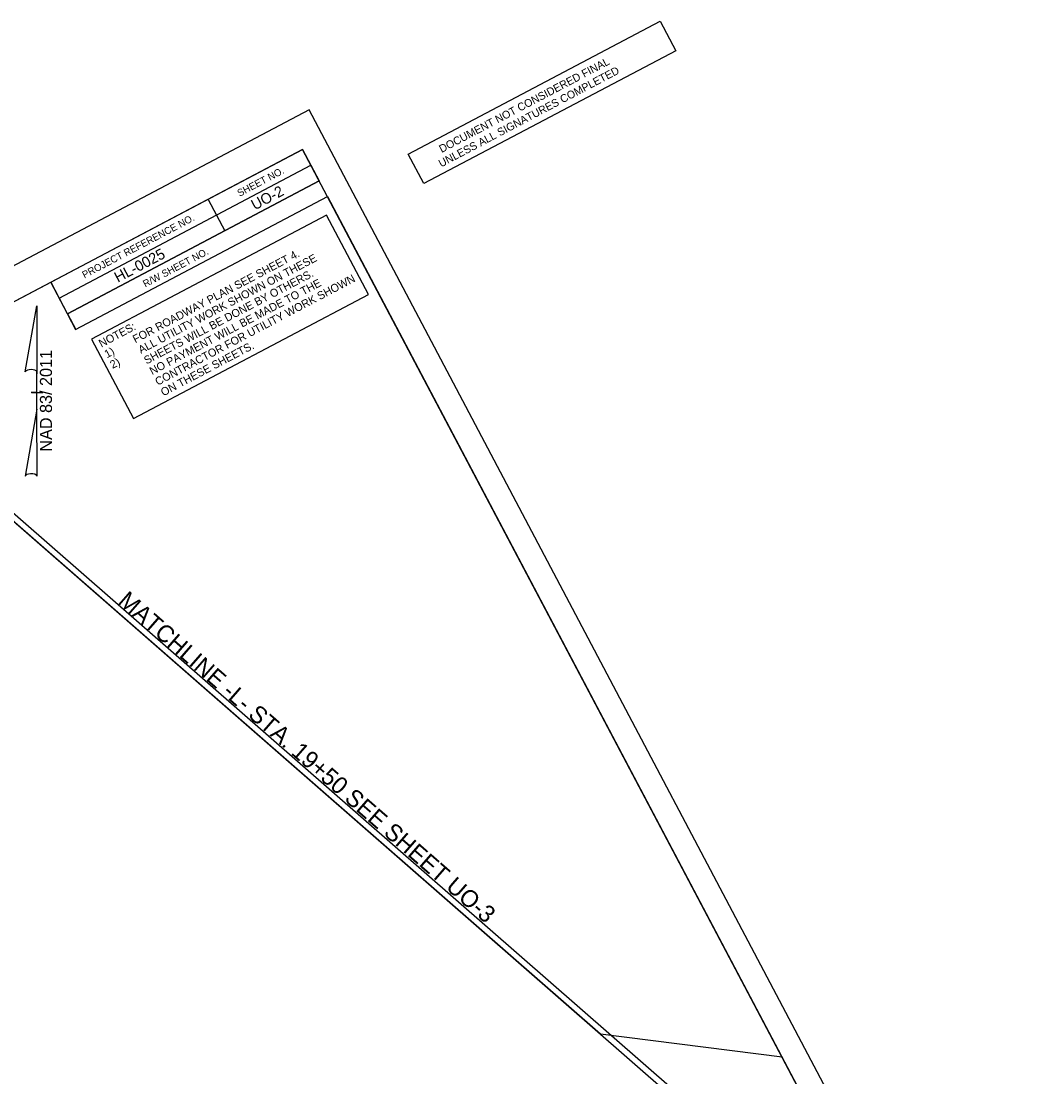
# Model space of a CAD drawing. Extents: x 1487051 to 1489241, y 497582 to 499399.
# Drawn here: x 1488337 to 1489051, y 498657 to 499399 of the extents above; entities that cross this region are included whole.
import ezdxf

# ---------------------------------------------------------------- set-up
doc = ezdxf.new("R2010")
doc.units = 0
for name, color, linetype in [('COGO Default Point Elevation', 7, 'Continuous'), ('Exist DTM Breakline Cogo Elevation', 7, 'Continuous'), ('Exist DTM Breakline Cogo Number', 7, 'Continuous'), ('Exist DTM Regular Point Cogo Elevation', 7, 'Continuous'), ('Exist DTM Regular Point Cogo Number', 7, 'Continuous'), ('Exist Other Culture Sign Post Cogo Comment', 7, 'Continuous'), ('Exist Roads EOP Cogo Elevation', 7, 'Continuous'), ('Exist Roads EOP Cogo Point CELL', 7, 'Continuous'), ('Exist Structure Minor Pipes RCP 15 Inch Cogo Comment', 7, 'Continuous'), ('Exist Vegetation Woods Line Cogo Comment', 7, 'Continuous'), ('Exist Vegetation Woods Line Cogo Elevation', 7, 'Continuous'), ('Exist Vegetation Woods Line Cogo Point CELL', 7, 'Continuous')]:
    doc.layers.add(name, color=color, linetype=linetype)

msp = doc.modelspace()

# ---------------------------------------------------------------- linework, layer by layer
at = {"layer": 'Exist DTM Breakline Cogo Number'}
msp.add_line((1488369.9, 499192.95), (1488375.74, 499181.9), dxfattribs=at)
at = {"layer": 'Exist DTM Regular Point Cogo Elevation'}
for points in [[(1487208.66, 498608.09), (1488222.07, 499143.23), (1488965.37, 498493.68), (1489025.39, 498380), (1487698.94, 497679.61)], [(1487208.66, 498608.09), (1488222.07, 499143.23), (1488965.37, 498493.68), (1489025.39, 498380), (1487698.94, 497679.61)], [(1487214.01, 498609.18), (1488227.42, 499144.32), (1488970.72, 498494.78), (1489030.74, 498381.1), (1487704.3, 497680.71)]]:
    msp.add_lwpolyline(points, close=True, dxfattribs=at)
at = {"layer": 'Exist Other Culture Sign Post Cogo Comment'}
msp.add_lwpolyline([(1488264.23, 499106.38), (1488223.12, 499143.79), (1487208.65, 498608.11), (1487698.94, 497679.61), (1489025.4, 498380.01), (1488871.95, 498670.61), (1488744.3, 498686.86)], close=True, dxfattribs=at)
at = {"layer": 'Exist Roads EOP Cogo Elevation'}
for p, q in [((1488609.36, 499305.26), (1488786.25, 499398.66)), ((1488786.26, 499398.65), (1488797.23, 499377.87)), ((1488797.23, 499377.88), (1488620.34, 499284.47)), ((1488620.34, 499284.47), (1488609.36, 499305.26))]:
    msp.add_line(p, q, dxfattribs=at)
at = {"layer": 'Exist Roads EOP Cogo Point CELL'}
msp.add_lwpolyline([(1487562.23, 497581.96), (1489050.94, 498368.04), (1488539.66, 499336.34), (1487050.94, 498550.27)], close=True, dxfattribs=at)
at = {"layer": 'Exist Structure Minor Pipes RCP 15 Inch Cogo Comment'}
for p, q in [((1488364.06, 499204.02), (1488540.97, 499297.41)), ((1488369.93, 499192.94), (1488546.81, 499286.36)), ((1488369.93, 499192.94), (1488546.81, 499286.36)), ((1488375.74, 499181.9), (1488552.62, 499275.32)), ((1488468.8, 499273.43), (1488480.51, 499251.34)), ((1488369.93, 499192.94), (1488375.76, 499181.89))]:
    msp.add_line(p, q, dxfattribs=at)
for points in [[(1488535.14, 499308.53), (1487208.67, 498608.12), (1487698.94, 497679.61), (1489025.4, 498380.01)], [(1488358.21, 499215.12), (1488535.14, 499308.53), (1488546.81, 499286.36), (1488369.93, 499192.94)], [(1487698.94, 497679.61), (1487208.66, 498608.09), (1488358.21, 499215.12), (1488375.74, 499181.9), (1488552.62, 499275.32), (1489025.4, 498380.01)]]:
    msp.add_lwpolyline(points, close=True, dxfattribs=at)
at = {"layer": 'Exist Vegetation Woods Line Cogo Comment'}
msp.add_line((1488264.23, 499106.38), (1488744.3, 498686.86), dxfattribs=at)
at = {"layer": 'Exist Vegetation Woods Line Cogo Elevation'}
msp.add_lwpolyline([(1488416.3, 499119.39), (1488581.38, 499206.59), (1488551.96, 499262.28), (1488386.88, 499175.09)], close=True, dxfattribs=at)
at = {"layer": 'Exist Vegetation Woods Line Cogo Point CELL'}
for p, q in [((1488340.33, 499152.33), (1488348.53, 499198.68)), ((1488348.58, 499198.68), (1488348.53, 499198.68)), ((1488348.58, 499198.68), (1488348.53, 499198.68)), ((1488348.58, 499198.68), (1488348.58, 499150.88)), ((1488348.58, 499126.08), (1488348.58, 499152.28)), ((1488348.58, 499150.88), (1488348.58, 499152.23)), ((1488344.58, 499137.68), (1488344.53, 499137.68)), ((1488348.13, 499137.68), (1488344.58, 499137.68)), ((1488344.63, 499137.68), (1488352.63, 499137.68)), ((1488348.58, 499126.08), (1488340.23, 499078.83)), ((1488348.63, 499079.03), (1488348.58, 499126.08))]:
    msp.add_line(p, q, dxfattribs=at)
for centre, start_param, end_param in [((1488344.46, 499151.83), 0.216388, 2.908219), ((1488344.46, 499078.66), 0.201328, 3.141593)]:
    msp.add_ellipse(centre, major_axis=(4.23, -0.03), ratio=0.461098, start_param=start_param, end_param=end_param, dxfattribs=at)

# ---------------------------------------------------------------- texts
at = {"layer": 'COGO Default Point Elevation'}
for s, p in [('FOR ROADWAY PLAN SEE SHEET 4.', (1488417.64, 499172.24)), ('ALL UTILITY WORK SHOWN ON THESE', (1488421.58, 499164.78)), ('SHEETS WILL BE DONE BY OTHERS.', (1488425.53, 499157.32)), ('NO PAYMENT WILL BE MADE TO THE', (1488429.47, 499149.86)), ('CONTRACTOR FOR UTILITY WORK SHOWN', (1488433.41, 499142.4)), ('NOTES:', (1488393.81, 499169.19)), ('1)', (1488397.75, 499161.73)), ('ON THESE SHEETS.', (1488437.35, 499134.94)), ('2)', (1488401.69, 499154.27))]:
    msp.add_text(s, height=5.625, rotation=27.84225, dxfattribs=at).set_placement(p)
at = {"layer": 'Exist DTM Breakline Cogo Elevation'}
for s, p in [('UO-2', (1488501.51, 499265.61)), ('HL-0025', (1488405.34, 499214.76))]:
    msp.add_text(s, height=7.5, rotation=27.8351, dxfattribs=at).set_placement(p)
at = {"layer": 'Exist DTM Regular Point Cogo Number'}
msp.add_text('MATCHLINE -L- STA. 19+50 SEE SHEET UO-3', height=12, rotation=318.92761, dxfattribs=at).set_placement((1488404.83, 498989.97))
at = {"layer": 'Exist Roads EOP Cogo Elevation'}
for s, p in [('UNLESS ALL SIGNATURES COMPLETED', (1488632.45, 499295.8)), ('DOCUMENT NOT CONSIDERED FINAL', (1488632.83, 499305.95))]:
    msp.add_text(s, height=5.5, rotation=27.83509, dxfattribs=at).set_placement(p)
at = {"layer": 'Exist Structure Minor Pipes RCP 15 Inch Cogo Comment'}
for s, height, p in [('SHEET NO.', 5, (1488490.88, 499275.18)), ('PROJECT REFERENCE NO.', 5.0001, (1488381.92, 499217.77)), ('R/W SHEET NO.', 5.0001, (1488424.62, 499211.43))]:
    msp.add_text(s, height=height, rotation=27.8351, dxfattribs=at).set_placement(p)
at = {"layer": 'Exist Vegetation Woods Line Cogo Point CELL'}
msp.add_text('NAD 83/ 2011', height=8.5, rotation=90, dxfattribs=at).set_placement((1488359.1, 499096.16))

doc.saveas('drawing.dxf')
